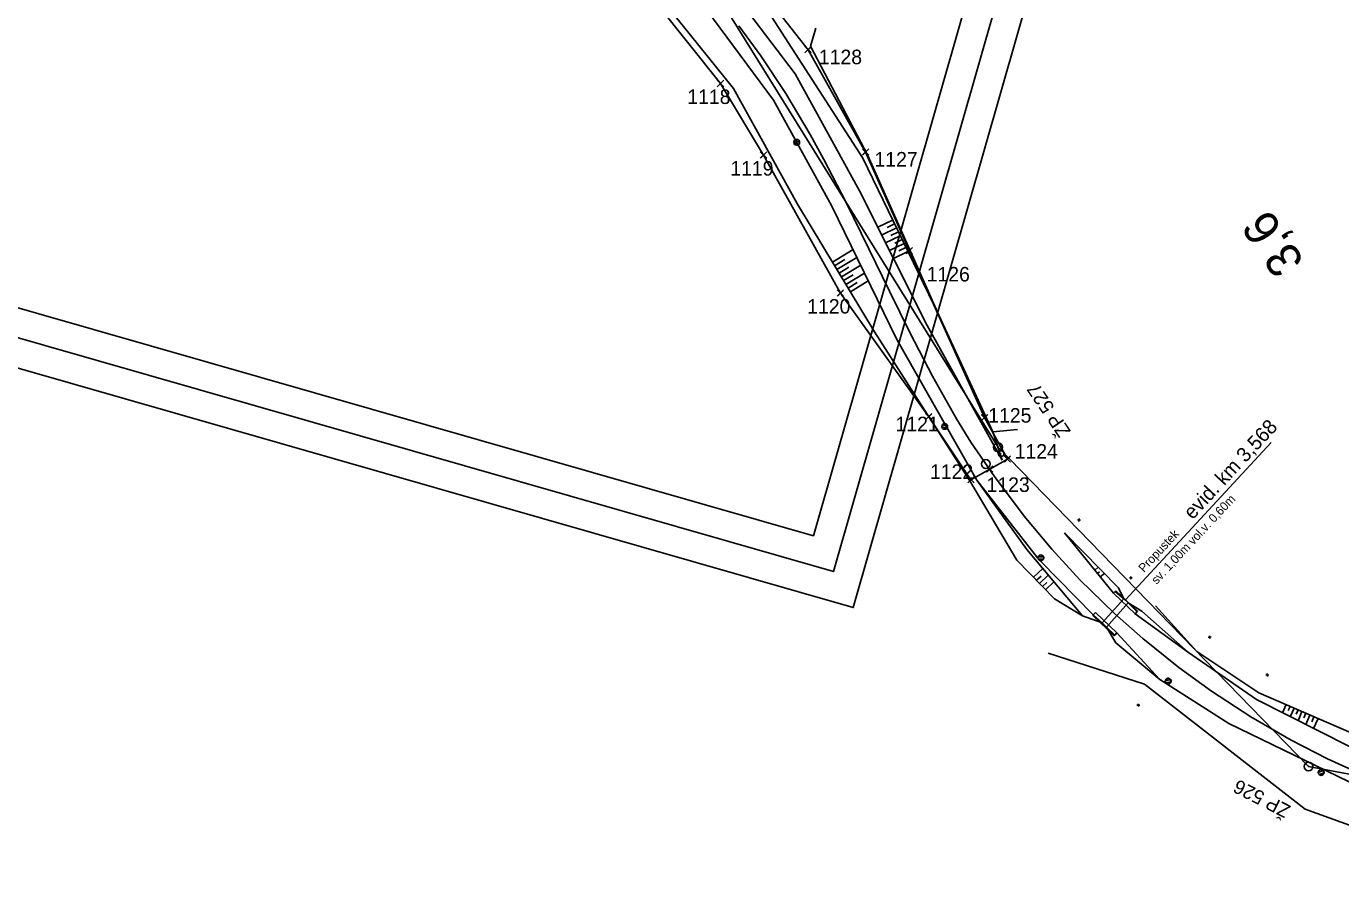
# Model space of a CAD drawing. Extents: x -738085 to -734426, y -1122197 to -1119748.
# Drawn here: x -736950.7 to -736724.2, y -1121765.3 to -1121615.9 of the extents above; entities that cross this region are included whole.
import ezdxf

# ---------------------------------------------------------------- set-up
doc = ezdxf.new("R2010")
doc.units = 0
for name, color, linetype in [('SŽDC', 7, 'Continuous'), ('Vrstva 1', 7, 'Continuous'), ('Vrstva 11', 7, 'Continuous'), ('Vrstva 12', 7, 'Continuous'), ('Vrstva 17', 7, 'Continuous'), ('Vrstva 19', 7, 'Continuous'), ('Vrstva 48', 7, 'Continuous'), ('Vrstva 49', 7, 'Continuous'), ('Vrstva 60', 7, 'Continuous'), ('Vrstva 63', 7, 'Continuous'), ('Vrstva 7', 7, 'Continuous')]:
    doc.layers.add(name, color=color, linetype=linetype)

msp = doc.modelspace()

# ---------------------------------------------------------------- linework, layer by layer
at = {"layer": 'SŽDC'}
for p, q in [((-736816.01, -1121619.92), (-736806.1, -1121637.54)), ((-736806.1, -1121637.54), (-736798.56, -1121654.54))]:
    msp.add_line(p, q, dxfattribs=at)
for points in [[(-736851.83, -1121584.35), (-736845.88, -1121588.28), (-736826.87, -1121606.1), (-736816.01, -1121619.92)], [(-736823.69, -1121638.07), (-736831.1, -1121625.74), (-736842, -1121612.07)], [(-736787.95, -1121693.96), (-736795.22, -1121683.12), (-736810.44, -1121661.83), (-736823.69, -1121638.07)], [(-736798.56, -1121654.54), (-736785.62, -1121683.26), (-736781.66, -1121690.42)], [(-736781.66, -1121690.42), (-736784.72, -1121692.14), (-736787.95, -1121693.96)]]:
    msp.add_lwpolyline(points, dxfattribs=at)
at = {"layer": 'Vrstva 1'}
for points in [[(-736726.43, -1121430.48), (-737533.93, -1121199.12), (-737615.73, -1121484.62), (-736808.23, -1121715.98)], [(-737530.5, -1121205.3), (-736732.61, -1121433.9), (-736811.65, -1121709.79), (-737609.54, -1121481.19)], [(-736738.79, -1121437.33), (-737330, -1121267.94), (-737406.29, -1121534.23), (-736815.08, -1121703.62)]]:
    msp.add_lwpolyline(points, close=True, dxfattribs=at)
msp.add_lwpolyline([(-736720.34, -1121744.85), (-736726.52, -1121742.02), (-736732.78, -1121738.82), (-736739.75, -1121734.78), (-736746.5, -1121730.38), (-736752.15, -1121726.29), (-736758.31, -1121721.33), (-736763.2, -1121717.03), (-736769.17, -1121711.2), (-736774.04, -1121705.9), (-736778.8, -1121700.25), (-736783.92, -1121693.44), (-736787.95, -1121687.49), (-736790.42, -1121683.49), (-736794.6, -1121676.14), (-736798.44, -1121668.75), (-736802, -1121661.51), (-736805.53, -1121654.2), (-736809.5, -1121646.11), (-736813.27, -1121638.85), (-736815.64, -1121634.52), (-736819.82, -1121627.48), (-736824.16, -1121620.98), (-736827.96, -1121615.83)], dxfattribs=at)
msp.add_lwpolyline([(-736720.34, -1121744.85), (-736726.52, -1121742.02), (-736732.78, -1121738.82), (-736739.75, -1121734.78), (-736746.5, -1121730.38), (-736752.15, -1121726.29), (-736758.31, -1121721.33), (-736763.2, -1121717.03), (-736769.17, -1121711.2), (-736774.04, -1121705.9), (-736778.8, -1121700.25), (-736783.92, -1121693.44), (-736787.95, -1121687.49), (-736790.42, -1121683.49), (-736794.6, -1121676.14), (-736798.44, -1121668.75), (-736802, -1121661.51), (-736805.53, -1121654.2), (-736809.5, -1121646.11), (-736813.27, -1121638.85), (-736815.64, -1121634.52), (-736819.82, -1121627.48), (-736824.16, -1121620.98), (-736827.96, -1121615.83)], dxfattribs=at)
at = {"layer": 'Vrstva 11'}
for p, q in [((-736817.59, -1121636.19), (-736818.47, -1121635.93)), ((-736817.48, -1121635.83), (-736818.37, -1121635.57)), ((-736792.08, -1121685.1), (-736792.97, -1121684.86)), ((-736791.98, -1121684.74), (-736792.87, -1121684.5)), ((-736775.46, -1121707.64), (-736776.38, -1121707.61)), ((-736775.44, -1121707.27), (-736776.37, -1121707.23)), ((-736753.53, -1121728.4), (-736754.44, -1121728.55)), ((-736753.48, -1121728.77), (-736754.38, -1121728.92)), ((-736727.25, -1121744.06), (-736728.11, -1121744.39)), ((-736727.12, -1121744.42), (-736727.98, -1121744.74))]:
    msp.add_line(p, q, dxfattribs=at)
for centre in [(-736817.97, -1121635.87), (-736792.47, -1121684.79), (-736775.91, -1121707.43), (-736753.96, -1121728.65), (-736727.62, -1121744.39)]:
    msp.add_circle(centre, 0.5, dxfattribs=at)
at = {"layer": 'Vrstva 12'}
for p, q in [((-736776.48, -1121707.41), (-736775.94, -1121708)), ((-736753.87, -1121729.21), (-736754.52, -1121728.74))]:
    msp.add_line(p, q, dxfattribs=at)
for points in [[(-736775.89, -1121706.86), (-736775.35, -1121707.45), (-736775.94, -1121708), (-736776.48, -1121707.41), (-736775.89, -1121706.86)], [(-736776.48, -1121707.41), (-736776.48, -1121707.41), (-736775.89, -1121706.86)], [(-736775.94, -1121708), (-736775.94, -1121708), (-736775.35, -1121707.45)], [(-736754.05, -1121728.09), (-736753.4, -1121728.56), (-736753.87, -1121729.21), (-736754.52, -1121728.74), (-736754.05, -1121728.09)], [(-736754.05, -1121728.09), (-736754.52, -1121728.74), (-736754.52, -1121728.74)], [(-736753.4, -1121728.56), (-736753.87, -1121729.21), (-736753.87, -1121729.21)]]:
    msp.add_lwpolyline(points, dxfattribs=at)
at = {"layer": 'Vrstva 17'}
for points in [[(-736793.5, -1121665.65), (-736805.7, -1121638.17), (-736815.61, -1121619.29), (-736814.67, -1121616.19)], [(-736779.91, -1121685.32), (-736784.17, -1121685.72), (-736793.5, -1121665.65)]]:
    msp.add_lwpolyline(points, dxfattribs=at)
at = {"layer": 'Vrstva 19'}
for p, q in [((-736761.31, -1121714.64), (-736736.21, -1121687.58)), ((-736765.34, -1121718.62), (-736761.62, -1121714.5)), ((-736765.34, -1121718.62), (-736761.62, -1121714.5)), ((-736763.38, -1121713.52), (-736762.97, -1121713.09)), ((-736759.67, -1121717.08), (-736763.38, -1121713.52)), ((-736762.97, -1121713.09), (-736759.23, -1121716.58)), ((-736762.97, -1121713.09), (-736759.23, -1121716.58)), ((-736766.98, -1121717.32), (-736766.52, -1121716.85)), ((-736766.88, -1121717.22), (-736766.52, -1121716.85)), ((-736766.52, -1121716.85), (-736762.79, -1121720.32)), ((-736764.62, -1121719.35), (-736760.87, -1121715.18)), ((-736764.62, -1121719.35), (-736760.87, -1121715.18)), ((-736759.23, -1121716.58), (-736759.67, -1121717.08)), ((-736759.33, -1121716.69), (-736759.67, -1121717.08)), ((-736766.98, -1121717.32), (-736766.88, -1121717.22)), ((-736763.25, -1121720.83), (-736766.98, -1121717.32)), ((-736763.25, -1121720.83), (-736766.98, -1121717.32)), ((-736766.98, -1121717.32), (-736766.98, -1121717.32)), ((-736765.34, -1121718.62), (-736766.88, -1121717.22)), ((-736766.88, -1121717.22), (-736766.88, -1121717.22)), ((-736763.15, -1121720.72), (-736766.88, -1121717.22)), ((-736763.15, -1121720.72), (-736764.62, -1121719.35)), ((-736762.79, -1121720.32), (-736763.25, -1121720.83)), ((-736763.15, -1121720.72), (-736762.79, -1121720.32)), ((-736763.15, -1121720.72), (-736763.15, -1121720.72))]:
    msp.add_line(p, q, dxfattribs=at)
for points in [[(-736762.97, -1121713.09), (-736763.08, -1121713.2), (-736763.08, -1121713.2), (-736763.38, -1121713.52)], [(-736759.23, -1121716.58), (-736759.33, -1121716.69), (-736759.33, -1121716.69), (-736760.87, -1121715.18), (-736760.87, -1121715.18), (-736761.62, -1121714.5), (-736761.62, -1121714.5), (-736763.08, -1121713.2)], [(-736759.23, -1121716.58), (-736759.23, -1121716.58), (-736762.97, -1121713.09), (-736762.97, -1121713.09)], [(-736764.62, -1121719.35), (-736764.62, -1121719.35), (-736765.34, -1121718.62), (-736765.34, -1121718.62)], [(-736763.15, -1121720.72), (-736763.25, -1121720.83), (-736763.25, -1121720.83)]]:
    msp.add_lwpolyline(points, dxfattribs=at)
at = {"layer": 'Vrstva 48'}
for p, q in [((-736801.44, -1121649.25), (-736804.01, -1121650.5)), ((-736800.79, -1121650.6), (-736803.34, -1121651.84)), ((-736801.11, -1121649.93), (-736802.4, -1121650.55)), ((-736800.46, -1121651.28), (-736801.73, -1121651.9)), ((-736800.13, -1121651.95), (-736802.67, -1121653.18)), ((-736799.48, -1121653.3), (-736801.99, -1121654.52)), ((-736799.81, -1121652.63), (-736801.07, -1121653.24)), ((-736811.82, -1121656.48), (-736808.27, -1121654.33)), ((-736811.05, -1121657.76), (-736807.61, -1121655.68)), ((-736798.83, -1121654.65), (-736801.32, -1121655.86)), ((-736799.15, -1121653.98), (-736800.4, -1121654.58)), ((-736811.44, -1121657.12), (-736809.69, -1121656.06)), ((-736810.66, -1121658.41), (-736808.97, -1121657.38)), ((-736810.27, -1121659.05), (-736806.95, -1121657.04)), ((-736809.88, -1121659.69), (-736808.25, -1121658.7)), ((-736809.49, -1121660.33), (-736806.29, -1121658.39)), ((-736809.1, -1121660.97), (-736807.53, -1121660.02)), ((-736808.71, -1121661.61), (-736805.63, -1121659.75)), ((-736777.17, -1121710.76), (-736775.59, -1121709.23)), ((-736766.61, -1121709.53), (-736766.01, -1121709.05)), ((-736766.14, -1121710.12), (-736765.81, -1121709.85)), ((-736765.67, -1121710.7), (-736764.96, -1121710.12)), ((-736776.64, -1121711.29), (-736775.88, -1121710.55)), ((-736776.12, -1121711.83), (-736774.63, -1121710.39)), ((-736775.6, -1121712.37), (-736774.87, -1121711.67)), ((-736775.08, -1121712.91), (-736773.67, -1121711.54)), ((-736733.67, -1121732.7), (-736734.28, -1121734.11)), ((-736732.98, -1121733), (-736733.3, -1121733.72)), ((-736732.29, -1121733.29), (-736732.94, -1121734.78)), ((-736731.6, -1121733.59), (-736731.94, -1121734.36)), ((-736730.92, -1121733.89), (-736731.6, -1121735.46)), ((-736730.23, -1121734.19), (-736730.58, -1121734.99)), ((-736729.54, -1121734.49), (-736730.26, -1121736.14)), ((-736728.85, -1121734.78), (-736729.22, -1121735.63)), ((-736728.16, -1121735.08), (-736728.91, -1121736.81))]:
    msp.add_line(p, q, dxfattribs=at)
at = {"layer": 'Vrstva 49'}
for p, q in [((-736769.09, -1121700.94), (-736769.59, -1121700.9)), ((-736769.36, -1121701.17), (-736769.32, -1121700.67)), ((-736763.38, -1121713.52), (-736771.81, -1121703.12)), ((-736760.15, -1121710.87), (-736760.64, -1121710.88)), ((-736760.39, -1121711.12), (-736760.4, -1121710.62)), ((-736749.02, -1121723.56), (-736756.18, -1121715.69)), ((-736746.57, -1121721.03), (-736747.07, -1121721.11)), ((-736746.78, -1121721.32), (-736746.86, -1121720.83)), ((-736758.07, -1121729.16), (-736774.64, -1121723.84)), ((-736736.65, -1121727.54), (-736737.14, -1121727.65)), ((-736736.84, -1121727.84), (-736736.94, -1121727.35)), ((-736758.88, -1121732.76), (-736759.37, -1121732.81)), ((-736759.1, -1121733.04), (-736759.15, -1121732.54))]:
    msp.add_line(p, q, dxfattribs=at)
for points in [[(-736782.58, -1121690.58), (-736795.5, -1121667.44), (-736807.17, -1121644.22), (-736818.23, -1121624.06), (-736830.45, -1121607.96), (-736849.48, -1121589.31), (-736871.46, -1121574.67), (-736894.77, -1121562.88), (-736918.94, -1121550.78), (-736938.32, -1121541.59), (-736947.56, -1121535.74), (-736946.88, -1121534.26), (-736947.22, -1121530.9)], [(-736765.34, -1121718.62), (-736768.76, -1121717.41), (-736778.32, -1121705.97), (-736786.95, -1121694.02), (-736800.73, -1121669.8), (-736811.97, -1121646.73), (-736821.95, -1121628.64), (-736834.59, -1121611.55), (-736852.32, -1121594.3), (-736852.93, -1121593.78), (-736853.86, -1121593.36), (-736873.78, -1121579.83), (-736896.64, -1121568.08), (-736921.16, -1121556.11), (-736944.74, -1121543.9), (-736949.24, -1121541.32), (-736966.17, -1121531.65)], [(-736944.71, -1121531.75), (-736944.12, -1121534.53), (-736945.03, -1121536.18), (-736937.72, -1121540.22), (-736918.35, -1121549.74), (-736893.95, -1121561.3), (-736870.26, -1121573.05), (-736848.96, -1121587.09), (-736826.36, -1121607.95), (-736806.6, -1121638.61), (-736793.5, -1121665.65), (-736784.17, -1121685.72), (-736782.58, -1121690.58)], [(-736948.26, -1121549.88), (-736946.95, -1121546.79), (-736945.91, -1121545.37), (-736898.27, -1121572.03), (-736870.86, -1121586.04), (-736857.62, -1121595.32), (-736839.16, -1121613.89), (-736828.86, -1121626.62), (-736817.85, -1121646.53), (-736804.54, -1121668.5), (-736788.17, -1121694.18), (-736780.03, -1121707.8), (-736773.57, -1121714.47), (-736768.76, -1121717.41)], [(-736765.34, -1121718.62), (-736766.88, -1121717.22), (-736775.94, -1121708), (-736776.48, -1121707.41), (-736786.95, -1121694.02)], [(-736761.62, -1121714.5), (-736762.55, -1121712.59), (-736771.81, -1121703.12)], [(-736763.38, -1121713.52), (-736763.08, -1121713.2), (-736761.62, -1121714.5)], [(-736750.48, -1121723.7), (-736758.52, -1121716.58), (-736760.87, -1121715.18)], [(-736750.48, -1121723.7), (-736759.67, -1121717.08), (-736759.33, -1121716.69), (-736760.87, -1121715.18)], [(-736755.42, -1121728.39), (-736762.97, -1121722.06), (-736764.62, -1121719.35)], [(-736755.42, -1121728.39), (-736762.79, -1121720.32), (-736763.15, -1121720.72), (-736764.62, -1121719.35)], [(-736750.48, -1121723.7), (-736738.78, -1121731.84), (-736711.92, -1121745.38), (-736698.08, -1121749.63), (-736678.89, -1121753.25), (-736659.63, -1121754.47), (-736639.02, -1121752.71), (-736619.52, -1121748.24), (-736612.09, -1121745.37)], [(-736613.54, -1121739.98), (-736613.76, -1121745.07), (-736620.01, -1121746.91), (-736639.26, -1121750.5), (-736661.81, -1121751.55), (-736678.85, -1121750.21), (-736697, -1121746.64), (-736710.41, -1121742.77), (-736738.37, -1121730.66), (-736749.02, -1121723.56)], [(-736602.93, -1121750.62), (-736617.95, -1121755.82), (-736639.5, -1121761.37), (-736654.03, -1121764.61), (-736658.53, -1121764.79), (-736677.92, -1121765.25), (-736698.72, -1121762.11), (-736730.37, -1121750.67), (-736758.07, -1121729.16)], [(-736602.93, -1121750.62), (-736618.59, -1121753.56), (-736637.64, -1121757.68), (-736638.02, -1121757.55), (-736638.82, -1121757.65), (-736659.7, -1121759.54), (-736670.41, -1121758.99), (-736671.41, -1121758.94), (-736678.34, -1121758.86), (-736698.35, -1121754.91), (-736698.8, -1121754.73), (-736699.57, -1121754.51), (-736713.56, -1121750.47), (-736743.53, -1121735.92), (-736755.42, -1121728.39)]]:
    msp.add_lwpolyline(points, dxfattribs=at)
at = {"layer": 'Vrstva 60'}
for p, q in [((-736815.56, -1121620.37), (-736816.56, -1121619.37)), ((-736815.56, -1121619.47), (-736816.56, -1121620.47)), ((-736816.46, -1121620.37), (-736815.46, -1121619.37)), ((-736816.46, -1121619.47), (-736815.46, -1121620.47)), ((-736816.01, -1121619.92), (-736816.01, -1121619.92)), ((-736830.65, -1121626.19), (-736831.65, -1121625.19)), ((-736830.65, -1121625.29), (-736831.65, -1121626.29)), ((-736831.55, -1121626.19), (-736830.55, -1121625.19)), ((-736831.55, -1121625.29), (-736830.55, -1121626.29)), ((-736831.1, -1121625.74), (-736831.1, -1121625.74)), ((-736823.24, -1121638.52), (-736824.24, -1121637.52)), ((-736823.24, -1121637.62), (-736824.24, -1121638.62)), ((-736824.14, -1121638.52), (-736823.14, -1121637.52)), ((-736824.14, -1121637.62), (-736823.14, -1121638.62)), ((-736805.65, -1121637.99), (-736806.65, -1121636.99)), ((-736805.65, -1121637.09), (-736806.65, -1121638.09)), ((-736806.55, -1121637.99), (-736805.55, -1121636.99)), ((-736806.55, -1121637.09), (-736805.55, -1121638.09)), ((-736806.1, -1121637.54), (-736806.1, -1121637.54)), ((-736823.69, -1121638.07), (-736823.69, -1121638.07)), ((-736798.11, -1121654.99), (-736799.11, -1121653.99)), ((-736798.11, -1121654.09), (-736799.11, -1121655.09)), ((-736799.01, -1121654.99), (-736798.01, -1121653.99)), ((-736799.01, -1121654.09), (-736798.01, -1121655.09)), ((-736798.56, -1121654.54), (-736798.56, -1121654.54)), ((-736809.99, -1121662.28), (-736810.99, -1121661.28)), ((-736809.99, -1121661.38), (-736810.99, -1121662.38)), ((-736810.89, -1121662.28), (-736809.89, -1121661.28)), ((-736810.89, -1121661.38), (-736809.89, -1121662.38)), ((-736810.44, -1121661.83), (-736810.44, -1121661.83)), ((-736794.77, -1121683.57), (-736795.77, -1121682.57)), ((-736794.77, -1121682.67), (-736795.77, -1121683.67)), ((-736795.67, -1121683.57), (-736794.67, -1121682.57)), ((-736795.67, -1121682.67), (-736794.67, -1121683.67)), ((-736785.17, -1121683.71), (-736786.17, -1121682.71)), ((-736785.17, -1121682.81), (-736786.17, -1121683.81)), ((-736786.07, -1121683.71), (-736785.07, -1121682.71)), ((-736786.07, -1121682.81), (-736785.07, -1121683.81)), ((-736795.22, -1121683.12), (-736795.22, -1121683.12)), ((-736785.62, -1121683.26), (-736785.62, -1121683.26)), ((-736784.27, -1121692.59), (-736785.27, -1121691.59)), ((-736784.27, -1121691.69), (-736785.27, -1121692.69)), ((-736785.17, -1121692.59), (-736784.17, -1121691.59)), ((-736785.17, -1121691.69), (-736784.17, -1121692.69)), ((-736781.21, -1121690.87), (-736782.21, -1121689.87)), ((-736781.21, -1121689.97), (-736782.21, -1121690.97)), ((-736782.11, -1121690.87), (-736781.11, -1121689.87)), ((-736782.11, -1121689.97), (-736781.11, -1121690.97)), ((-736781.66, -1121690.42), (-736781.66, -1121690.42)), ((-736787.5, -1121694.41), (-736788.5, -1121693.41)), ((-736787.5, -1121693.51), (-736788.5, -1121694.51)), ((-736788.4, -1121694.41), (-736787.4, -1121693.41)), ((-736788.4, -1121693.51), (-736787.4, -1121694.51)), ((-736787.95, -1121693.96), (-736787.95, -1121693.96)), ((-736784.72, -1121692.14), (-736784.72, -1121692.14))]:
    msp.add_line(p, q, dxfattribs=at)
at = {"layer": 'Vrstva 63'}
for p, q in [((-736844.93, -1121589.06), (-736783.29, -1121688.38)), ((-736783.34, -1121688.38), (-736783.24, -1121688.38)), ((-736783.29, -1121688.38), (-736729.78, -1121743.34)), ((-736729.74, -1121743.37), (-736729.83, -1121743.32)), ((-736729.78, -1121743.34), (-736634.91, -1121761.31))]:
    msp.add_line(p, q, dxfattribs=at)
for centre in [(-736783.29, -1121688.38), (-736729.78, -1121743.34)]:
    msp.add_circle(centre, 0.756, dxfattribs=at)
at = {"layer": 'Vrstva 7'}
msp.add_line((-736782.72, -1121689.52), (-736782.79, -1121689.44), dxfattribs=at)
for centre, radius in [((-736782.76, -1121689.48), 0.5), ((-736785.39, -1121691.26), 0.75), ((-736785.39, -1121691.26), 0.75)]:
    msp.add_circle(centre, radius, dxfattribs=at)

# ---------------------------------------------------------------- texts
at = {"layer": 'Vrstva 19'}
for s, height, rotation, p in [('evid. km 3,568', 2.5, 47.1494, (-736749.75, -1121700.96)), ('sv. 1,00m vol.v. 0,60m', 1.5, 47.0197, (-736755.95, -1121712.08)), ('Propustek', 1.5, 47.0197, (-736758.14, -1121710.03))]:
    msp.add_text(s, height=height, rotation=rotation, dxfattribs=at).set_placement(p)
at = {"layer": 'Vrstva 60'}
for s, p in [('1128', (-736814.15, -1121622.42)), ('1118', (-736836.82, -1121629.27)), ('1127', (-736804.57, -1121640.04)), ('1119', (-736829.41, -1121641.6)), ('1126', (-736795.58, -1121659.83)), ('1120', (-736816.16, -1121665.36)), ('1125', (-736784.97, -1121684.14)), ('1121', (-736800.94, -1121685.62)), ('1124', (-736780.42, -1121690.34)), ('1122', (-736795.01, -1121693.83)), ('1123', (-736785.26, -1121696.07))]:
    msp.add_text(s, height=2.5, dxfattribs=at).set_placement(p)
at = {"layer": 'Vrstva 63'}
for s, rotation, p in [('ŽP 527', 124.1319, (-736770.66, -1121685.63)), ('ŽP 526', 152.9034, (-736732.7, -1121750.2))]:
    msp.add_text(s, height=2.4, rotation=rotation, dxfattribs=at).set_placement(p)
at = {"layer": 'Vrstva 7'}
msp.add_text('3,6', height=6, rotation=124.1319, dxfattribs=at).set_placement((-736730.36, -1121656.36))
msp.add_text('3,6', height=6, rotation=124.1319, dxfattribs=at).set_placement((-736730.36, -1121656.36))

doc.saveas('drawing.dxf')
